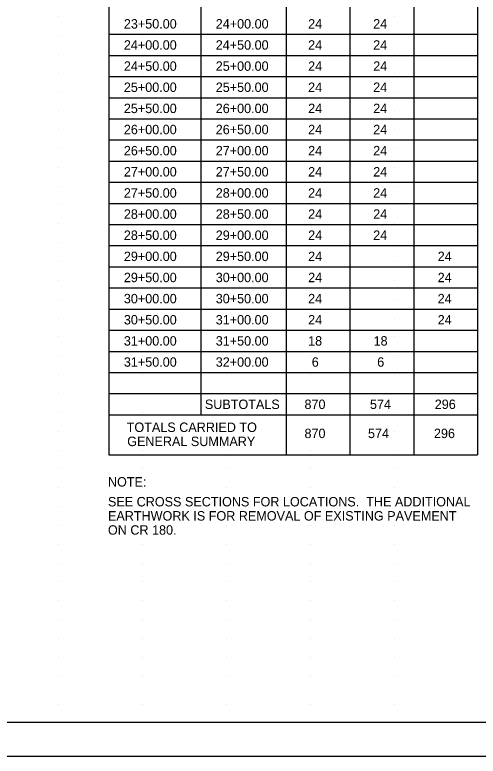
# Model space of a CAD drawing. Extents: x 2073163.9 to 2073197.9, y 634076.5 to 634098.5.
# Drawn here: x 2073184.67 to 2073191.56, y 634076.55 to 634087.56 of the extents above; entities that cross this region are included whole.
import ezdxf

# ---------------------------------------------------------------- set-up
doc = ezdxf.new("R2010")
doc.units = 0
for name, color, linetype in [('SH_Border', 7, 'Continuous'), ('SH_Cut_Line', 7, 'Continuous'), ('SH_Data', 7, 'Continuous'), ('SH_Text', 7, 'Continuous')]:
    doc.layers.add(name, color=color, linetype=linetype)

msp = doc.modelspace()

# ---------------------------------------------------------------- linework, layer by layer
at = {"layer": 'SH_Border'}
for p, q in [((2073186.071, 634097.55), (2073186.071, 634081.026)), ((2073191.547, 634097.55), (2073191.547, 634081.026)), ((2073186.071, 634081.026), (2073191.547, 634081.026))]:
    msp.add_line(p, q, dxfattribs=at)
msp.add_lwpolyline([(2073165.446, 634098.05), (2073197.446, 634098.05), (2073197.446, 634077.05), (2073165.446, 634077.05)], close=True, dxfattribs=at)
at = {"layer": 'SH_Cut_Line'}
msp.add_lwpolyline([(2073163.946, 634076.55), (2073197.946, 634076.55), (2073197.946, 634098.55), (2073163.946, 634098.55)], close=True, dxfattribs=at)
at = {"layer": 'SH_Data'}
for p, q in [((2073185.321, 634087.538), (2073185.321, 634087.538)), ((2073186.571, 634087.538), (2073186.571, 634087.538)), ((2073187.821, 634087.538), (2073187.821, 634087.538)), ((2073189.071, 634087.538), (2073189.071, 634087.538)), ((2073190.321, 634087.538), (2073190.321, 634087.538)), ((2073185.321, 634087.258), (2073185.321, 634087.258)), ((2073186.571, 634087.258), (2073186.571, 634087.258)), ((2073187.821, 634087.258), (2073187.821, 634087.258)), ((2073189.071, 634087.258), (2073189.071, 634087.258)), ((2073190.321, 634087.258), (2073190.321, 634087.258)), ((2073185.321, 634086.978), (2073185.321, 634086.978)), ((2073186.571, 634086.978), (2073186.571, 634086.978)), ((2073187.821, 634086.978), (2073187.821, 634086.978)), ((2073189.071, 634086.978), (2073189.071, 634086.978)), ((2073190.321, 634086.978), (2073190.321, 634086.978)), ((2073185.321, 634086.698), (2073185.321, 634086.698)), ((2073186.571, 634086.698), (2073186.571, 634086.698)), ((2073187.821, 634086.698), (2073187.821, 634086.698)), ((2073189.071, 634086.698), (2073189.071, 634086.698)), ((2073190.321, 634086.698), (2073190.321, 634086.698)), ((2073185.321, 634086.418), (2073185.321, 634086.418)), ((2073186.571, 634086.418), (2073186.571, 634086.418)), ((2073187.821, 634086.418), (2073187.821, 634086.418)), ((2073189.071, 634086.418), (2073189.071, 634086.418)), ((2073190.321, 634086.418), (2073190.321, 634086.418)), ((2073185.321, 634086.138), (2073185.321, 634086.138)), ((2073186.571, 634086.138), (2073186.571, 634086.138)), ((2073187.821, 634086.138), (2073187.821, 634086.138)), ((2073189.071, 634086.138), (2073189.071, 634086.138)), ((2073190.321, 634086.138), (2073190.321, 634086.138)), ((2073185.321, 634085.858), (2073185.321, 634085.858)), ((2073186.571, 634085.858), (2073186.571, 634085.858)), ((2073187.821, 634085.858), (2073187.821, 634085.858)), ((2073189.071, 634085.858), (2073189.071, 634085.858)), ((2073190.321, 634085.858), (2073190.321, 634085.858)), ((2073185.321, 634085.578), (2073185.321, 634085.578)), ((2073186.571, 634085.578), (2073186.571, 634085.578)), ((2073187.821, 634085.578), (2073187.821, 634085.578)), ((2073189.071, 634085.578), (2073189.071, 634085.578)), ((2073190.321, 634085.578), (2073190.321, 634085.578)), ((2073185.321, 634085.298), (2073185.321, 634085.298)), ((2073186.571, 634085.298), (2073186.571, 634085.298)), ((2073187.821, 634085.298), (2073187.821, 634085.298)), ((2073189.071, 634085.298), (2073189.071, 634085.298)), ((2073190.321, 634085.298), (2073190.321, 634085.298)), ((2073185.321, 634085.018), (2073185.321, 634085.018)), ((2073186.571, 634085.018), (2073186.571, 634085.018)), ((2073187.821, 634085.018), (2073187.821, 634085.018)), ((2073189.071, 634085.018), (2073189.071, 634085.018)), ((2073190.321, 634085.018), (2073190.321, 634085.018)), ((2073185.321, 634084.738), (2073185.321, 634084.738)), ((2073186.571, 634084.738), (2073186.571, 634084.738)), ((2073187.821, 634084.738), (2073187.821, 634084.738)), ((2073189.071, 634084.738), (2073189.071, 634084.738)), ((2073190.321, 634084.738), (2073190.321, 634084.738)), ((2073185.321, 634084.458), (2073185.321, 634084.458)), ((2073186.571, 634084.458), (2073186.571, 634084.458)), ((2073187.821, 634084.458), (2073187.821, 634084.458)), ((2073189.071, 634084.458), (2073189.071, 634084.458)), ((2073190.321, 634084.458), (2073190.321, 634084.458)), ((2073185.321, 634084.178), (2073185.321, 634084.178)), ((2073186.571, 634084.178), (2073186.571, 634084.178)), ((2073187.821, 634084.178), (2073187.821, 634084.178)), ((2073189.071, 634084.178), (2073189.071, 634084.178)), ((2073190.321, 634084.178), (2073190.321, 634084.178)), ((2073185.321, 634083.898), (2073185.321, 634083.898)), ((2073186.571, 634083.898), (2073186.571, 634083.898)), ((2073187.821, 634083.898), (2073187.821, 634083.898)), ((2073189.071, 634083.898), (2073189.071, 634083.898)), ((2073190.321, 634083.898), (2073190.321, 634083.898)), ((2073185.321, 634083.618), (2073185.321, 634083.618)), ((2073186.571, 634083.618), (2073186.571, 634083.618)), ((2073187.821, 634083.618), (2073187.821, 634083.618)), ((2073189.071, 634083.618), (2073189.071, 634083.618)), ((2073190.321, 634083.618), (2073190.321, 634083.618)), ((2073185.321, 634083.338), (2073185.321, 634083.338)), ((2073186.571, 634083.338), (2073186.571, 634083.338)), ((2073187.821, 634083.338), (2073187.821, 634083.338)), ((2073189.071, 634083.338), (2073189.071, 634083.338)), ((2073190.321, 634083.338), (2073190.321, 634083.338)), ((2073185.321, 634083.058), (2073185.321, 634083.058)), ((2073186.571, 634083.058), (2073186.571, 634083.058)), ((2073187.821, 634083.058), (2073187.821, 634083.058)), ((2073189.071, 634083.058), (2073189.071, 634083.058)), ((2073190.321, 634083.058), (2073190.321, 634083.058)), ((2073185.321, 634082.778), (2073185.321, 634082.778)), ((2073186.571, 634082.778), (2073186.571, 634082.778)), ((2073187.821, 634082.778), (2073187.821, 634082.778)), ((2073189.071, 634082.778), (2073189.071, 634082.778)), ((2073190.321, 634082.778), (2073190.321, 634082.778)), ((2073185.321, 634082.498), (2073185.321, 634082.498)), ((2073186.571, 634082.498), (2073186.571, 634082.498)), ((2073187.821, 634082.498), (2073187.821, 634082.498)), ((2073189.071, 634082.498), (2073189.071, 634082.498)), ((2073190.321, 634082.498), (2073190.321, 634082.498)), ((2073185.321, 634082.218), (2073185.321, 634082.218)), ((2073186.571, 634082.218), (2073186.571, 634082.218)), ((2073187.821, 634082.218), (2073187.821, 634082.218)), ((2073189.071, 634082.218), (2073189.071, 634082.218)), ((2073190.321, 634082.218), (2073190.321, 634082.218)), ((2073185.321, 634081.938), (2073185.321, 634081.938)), ((2073186.571, 634081.938), (2073186.571, 634081.938)), ((2073187.821, 634081.938), (2073187.821, 634081.938)), ((2073189.071, 634081.938), (2073189.071, 634081.938)), ((2073190.321, 634081.938), (2073190.321, 634081.938)), ((2073185.321, 634081.658), (2073185.321, 634081.658)), ((2073186.571, 634081.658), (2073186.571, 634081.658)), ((2073187.821, 634081.658), (2073187.821, 634081.658)), ((2073189.071, 634081.658), (2073189.071, 634081.658)), ((2073190.321, 634081.658), (2073190.321, 634081.658)), ((2073185.321, 634081.378), (2073185.321, 634081.378)), ((2073186.571, 634081.378), (2073186.571, 634081.378)), ((2073187.821, 634081.378), (2073187.821, 634081.378)), ((2073189.071, 634081.378), (2073189.071, 634081.378)), ((2073190.321, 634081.378), (2073190.321, 634081.378)), ((2073185.321, 634081.098), (2073185.321, 634081.098)), ((2073186.571, 634081.098), (2073186.571, 634081.098)), ((2073187.821, 634081.098), (2073187.821, 634081.098)), ((2073189.071, 634081.098), (2073189.071, 634081.098)), ((2073190.321, 634081.098), (2073190.321, 634081.098)), ((2073185.321, 634080.818), (2073185.321, 634080.818)), ((2073186.571, 634080.818), (2073186.571, 634080.818)), ((2073187.821, 634080.818), (2073187.821, 634080.818)), ((2073189.071, 634080.818), (2073189.071, 634080.818)), ((2073190.321, 634080.818), (2073190.321, 634080.818)), ((2073185.321, 634080.538), (2073185.321, 634080.538)), ((2073186.571, 634080.538), (2073186.571, 634080.538)), ((2073187.821, 634080.538), (2073187.821, 634080.538)), ((2073189.071, 634080.538), (2073189.071, 634080.538)), ((2073190.321, 634080.538), (2073190.321, 634080.538)), ((2073185.321, 634080.258), (2073185.321, 634080.258)), ((2073186.571, 634080.258), (2073186.571, 634080.258)), ((2073187.821, 634080.258), (2073187.821, 634080.258)), ((2073189.071, 634080.258), (2073189.071, 634080.258)), ((2073190.321, 634080.258), (2073190.321, 634080.258)), ((2073185.321, 634079.978), (2073185.321, 634079.978)), ((2073186.571, 634079.978), (2073186.571, 634079.978)), ((2073187.821, 634079.978), (2073187.821, 634079.978)), ((2073189.071, 634079.978), (2073189.071, 634079.978)), ((2073190.321, 634079.978), (2073190.321, 634079.978)), ((2073185.321, 634079.698), (2073185.321, 634079.698)), ((2073186.571, 634079.698), (2073186.571, 634079.698)), ((2073187.821, 634079.698), (2073187.821, 634079.698)), ((2073189.071, 634079.698), (2073189.071, 634079.698)), ((2073190.321, 634079.698), (2073190.321, 634079.698)), ((2073185.321, 634079.418), (2073185.321, 634079.418)), ((2073186.571, 634079.418), (2073186.571, 634079.418)), ((2073187.821, 634079.418), (2073187.821, 634079.418)), ((2073189.071, 634079.418), (2073189.071, 634079.418)), ((2073190.321, 634079.418), (2073190.321, 634079.418)), ((2073185.321, 634079.138), (2073185.321, 634079.138)), ((2073186.571, 634079.138), (2073186.571, 634079.138)), ((2073187.821, 634079.138), (2073187.821, 634079.138)), ((2073189.071, 634079.138), (2073189.071, 634079.138)), ((2073190.321, 634079.138), (2073190.321, 634079.138)), ((2073185.321, 634078.858), (2073185.321, 634078.858)), ((2073186.571, 634078.858), (2073186.571, 634078.858)), ((2073187.821, 634078.858), (2073187.821, 634078.858)), ((2073189.071, 634078.858), (2073189.071, 634078.858)), ((2073190.321, 634078.858), (2073190.321, 634078.858)), ((2073185.321, 634078.578), (2073185.321, 634078.578)), ((2073186.571, 634078.578), (2073186.571, 634078.578)), ((2073187.821, 634078.578), (2073187.821, 634078.578)), ((2073189.071, 634078.578), (2073189.071, 634078.578)), ((2073190.321, 634078.578), (2073190.321, 634078.578)), ((2073185.321, 634078.298), (2073185.321, 634078.298)), ((2073186.571, 634078.298), (2073186.571, 634078.298)), ((2073187.821, 634078.298), (2073187.821, 634078.298)), ((2073189.071, 634078.298), (2073189.071, 634078.298)), ((2073190.321, 634078.298), (2073190.321, 634078.298)), ((2073185.321, 634078.018), (2073185.321, 634078.018)), ((2073186.571, 634078.018), (2073186.571, 634078.018)), ((2073187.821, 634078.018), (2073187.821, 634078.018)), ((2073189.071, 634078.018), (2073189.071, 634078.018)), ((2073190.321, 634078.018), (2073190.321, 634078.018)), ((2073185.321, 634077.738), (2073185.321, 634077.738)), ((2073186.571, 634077.738), (2073186.571, 634077.738)), ((2073187.821, 634077.738), (2073187.821, 634077.738)), ((2073189.071, 634077.738), (2073189.071, 634077.738)), ((2073190.321, 634077.738), (2073190.321, 634077.738)), ((2073185.321, 634077.324), (2073185.321, 634077.324)), ((2073186.571, 634077.324), (2073186.571, 634077.324)), ((2073187.821, 634077.324), (2073187.821, 634077.324)), ((2073189.071, 634077.324), (2073189.071, 634077.324)), ((2073190.321, 634077.324), (2073190.321, 634077.324))]:
    msp.add_line(p, q, dxfattribs=at)
at = {"layer": 'SH_Text'}
for p, q in [((2073188.706, 634097.236), (2073188.706, 634081.026)), ((2073189.653, 634096.922), (2073189.653, 634081.026)), ((2073190.6, 634096.922), (2073190.6, 634081.026)), ((2073187.436, 634095.125), (2073187.436, 634081.621)), ((2073186.071, 634087.274), (2073191.547, 634087.274)), ((2073186.071, 634086.96), (2073191.547, 634086.96)), ((2073186.071, 634086.646), (2073191.547, 634086.646)), ((2073186.071, 634086.332), (2073191.547, 634086.332)), ((2073186.071, 634086.018), (2073191.547, 634086.018)), ((2073186.071, 634085.704), (2073191.547, 634085.704)), ((2073186.071, 634085.39), (2073191.547, 634085.39)), ((2073186.071, 634085.076), (2073191.547, 634085.076)), ((2073186.071, 634084.762), (2073191.547, 634084.762)), ((2073186.071, 634084.448), (2073191.547, 634084.448)), ((2073186.071, 634084.134), (2073191.547, 634084.134)), ((2073186.071, 634083.819), (2073191.547, 634083.819)), ((2073186.071, 634083.505), (2073191.547, 634083.505)), ((2073186.071, 634083.191), (2073191.547, 634083.191)), ((2073186.071, 634082.877), (2073191.547, 634082.877)), ((2073186.071, 634082.563), (2073191.547, 634082.563)), ((2073186.071, 634082.249), (2073191.547, 634082.249)), ((2073186.071, 634081.935), (2073191.547, 634081.935)), ((2073186.071, 634081.621), (2073191.547, 634081.621))]:
    msp.add_line(p, q, dxfattribs=at)

# ---------------------------------------------------------------- texts
for s, p in [('23+50.00', (2073186.292, 634087.359)), ('24+00.00', (2073187.658, 634087.359)), ('24', (2073189.031, 634087.359)), ('24', (2073189.998, 634087.359)), ('24+00.00', (2073186.292, 634087.045)), ('24+50.00', (2073187.658, 634087.045)), ('24', (2073189.031, 634087.045)), ('24', (2073189.998, 634087.045)), ('24+50.00', (2073186.292, 634086.731)), ('25+00.00', (2073187.658, 634086.731)), ('24', (2073189.031, 634086.731)), ('24', (2073189.998, 634086.731)), ('25+00.00', (2073186.292, 634086.417)), ('25+50.00', (2073187.658, 634086.417)), ('24', (2073189.031, 634086.417)), ('24', (2073189.998, 634086.417)), ('25+50.00', (2073186.292, 634086.103)), ('26+00.00', (2073187.658, 634086.103)), ('24', (2073189.031, 634086.103)), ('24', (2073189.998, 634086.103)), ('26+00.00', (2073186.292, 634085.789)), ('26+50.00', (2073187.658, 634085.789)), ('24', (2073189.031, 634085.789)), ('24', (2073189.998, 634085.789)), ('26+50.00', (2073186.292, 634085.475)), ('27+00.00', (2073187.658, 634085.475)), ('24', (2073189.031, 634085.475)), ('24', (2073189.998, 634085.475)), ('27+00.00', (2073186.292, 634085.161)), ('27+50.00', (2073187.658, 634085.161)), ('24', (2073189.031, 634085.161)), ('24', (2073189.998, 634085.161)), ('27+50.00', (2073186.292, 634084.847)), ('28+00.00', (2073187.658, 634084.847)), ('24', (2073189.031, 634084.847)), ('24', (2073189.998, 634084.847)), ('28+00.00', (2073186.292, 634084.533)), ('28+50.00', (2073187.658, 634084.533)), ('24', (2073189.031, 634084.533)), ('24', (2073189.998, 634084.533)), ('28+50.00', (2073186.292, 634084.219)), ('29+00.00', (2073187.658, 634084.219)), ('24', (2073189.031, 634084.219)), ('24', (2073189.998, 634084.219)), ('29+00.00', (2073186.292, 634083.905)), ('29+50.00', (2073187.658, 634083.905)), ('24', (2073189.031, 634083.905)), ('24', (2073190.957, 634083.905)), ('29+50.00', (2073186.292, 634083.591)), ('30+00.00', (2073187.658, 634083.591)), ('24', (2073189.031, 634083.591)), ('24', (2073190.957, 634083.591)), ('30+00.00', (2073186.292, 634083.277)), ('30+50.00', (2073187.658, 634083.277)), ('24', (2073189.031, 634083.277)), ('24', (2073190.957, 634083.277)), ('30+50.00', (2073186.292, 634082.963)), ('31+00.00', (2073187.658, 634082.963)), ('24', (2073189.031, 634082.963)), ('24', (2073190.957, 634082.963)), ('31+00.00', (2073186.292, 634082.649)), ('31+50.00', (2073187.658, 634082.649)), ('18', (2073189.031, 634082.649)), ('18', (2073190.004, 634082.649)), ('31+50.00', (2073186.292, 634082.335)), ('32+00.00', (2073187.658, 634082.335)), ('6', (2073189.085, 634082.335)), ('6', (2073190.058, 634082.335)), ('SUBTOTALS', (2073187.496, 634081.707)), ('870', (2073188.977, 634081.707)), ('574', (2073189.95, 634081.707)), ('296', (2073190.913, 634081.707)), ('TOTALS CARRIED TO ', (2073186.335, 634081.366)), ('870', (2073188.977, 634081.275)), ('574', (2073189.921, 634081.275)), ('296', (2073190.901, 634081.275)), ('GENERAL SUMMARY', (2073186.342, 634081.156)), ('NOTE:', (2073186.056, 634080.555)), ('SEE CROSS SECTIONS FOR LOCATIONS.  THE ADDITIONAL', (2073186.056, 634080.26)), ('EARTHWORK IS FOR REMOVAL OF EXISTING PAVEMENT ', (2073186.056, 634080.05)), ('ON CR 180.', (2073186.056, 634079.84))]:
    msp.add_text(s, height=0.14, dxfattribs=at).set_placement(p)

doc.saveas('drawing.dxf')
